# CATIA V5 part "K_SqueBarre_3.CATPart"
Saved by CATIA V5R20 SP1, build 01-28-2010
Part number: squelette_barre_3
Publications: "Point.1", "Point.2", "Droite.1", "Plan.1", "Droite.2", "Droite.3"
Bounding box of the stored display mesh (mm): x 0 to 0, y 0 to 20, z 0 to 50
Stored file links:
  G:\Khaled_CFAO_2011\ST2M\ST2M_GR2\gcausse\Khaled\CAD_ThinkMotion\K_SqueBarre_3.CATPart
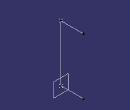
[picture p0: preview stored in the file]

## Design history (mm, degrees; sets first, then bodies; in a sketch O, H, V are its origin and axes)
Set1
  Point1: (0, 0, 0)
  Point2: (0, 0, 50)
  Line1: type PtPt, FirstPoint Point2, SecondPoint Point1
  Plane1: type Offset, RefPlane zx-plane, Offset 0
  Line2: type PtDir, RefPoint Point2, Direction Plane1, Start 0, End 20
  Line3: type PtDir, RefPoint Point1, Direction Plane1, Start 0, End 20
Body1 (main body)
